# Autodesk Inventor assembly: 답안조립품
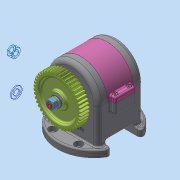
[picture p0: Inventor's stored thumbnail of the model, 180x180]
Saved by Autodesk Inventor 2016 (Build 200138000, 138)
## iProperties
Created: 2024-08
Part Number: 답안조립품
Material: 일반
Document SubType Name: Assembly
Designer: pc-7
Author: pc-7
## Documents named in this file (19)
- C:\Users\pc-7\Desktop\740804V1020\답안조립품.iam
- C:\Users\pc-7\Desktop\740804V1020\본체.ipt
- C:\Users\pc-7\Desktop\740804V1020\뒷커버.ipt
- C:\Users\pc-7\Desktop\740804V1020\앞커버.ipt
- C:\Users\pc-7\Desktop\740804V1020\부시 커버.ipt
- C:\Users\pc-7\Desktop\740804V1020\윗커버.ipt
- C:\Users\pc-7\Desktop\740804V1020\육각 소켓 머리 볼트 M4x10.ipt
- C:\Users\pc-7\Desktop\740804V1020\깊은 홈 볼 베어링 6904.ipt
- C:\Users\pc-7\Desktop\740804V1020\편심축.ipt
- C:\Users\pc-7\Desktop\740804V1020\링크.ipt
- C:\Users\pc-7\Desktop\740804V1020\펀치.ipt
- C:\Users\pc-7\Desktop\740804V1020\핀.ipt
- C:\Users\pc-7\Desktop\740804V1020\오일레스 부시 20 15.ipt
- C:\Users\pc-7\Desktop\740804V1020\오일실 20 32 5.ipt
- C:\Users\pc-7\Desktop\740804V1020\평행키 5x5x12.ipt
- C:\Users\pc-7\Desktop\740804V1020\스퍼 기어.ipt
- C:\Users\pc-7\Desktop\740804V1020\스프링 와셔 M10.ipt
- C:\Users\pc-7\Desktop\740804V1020\평와셔 M10.ipt
- C:\Users\pc-7\Desktop\740804V1020\육각 너트 M10x1.ipt
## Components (1 placed, 1 different names)
1. 핀:1
